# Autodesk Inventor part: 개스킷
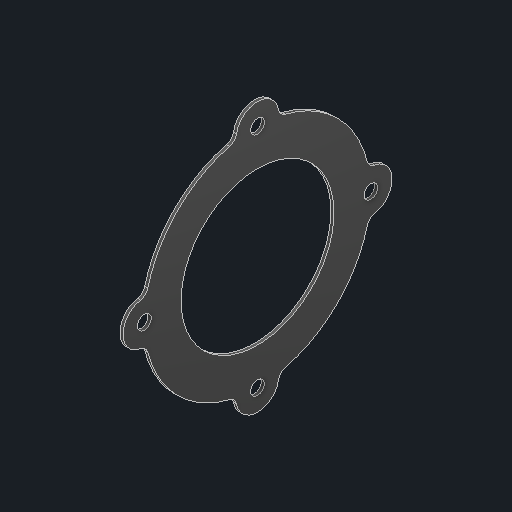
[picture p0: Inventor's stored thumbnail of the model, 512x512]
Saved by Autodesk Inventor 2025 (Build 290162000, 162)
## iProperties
Created: 2025-08
Part Number: 개스킷
Material: 황동, 연질 노란색
Document SubType Name: Modeling
Designer: infra08
Density: 8.47 g/cm^3
Appearance: 기본값
Author: jhkim
Sending System: Autodesk Inventor 2026
Preprocessor: ST-DEVELOPER v20.1
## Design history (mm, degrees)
feature "솔리드2"
node "솔리드1"
